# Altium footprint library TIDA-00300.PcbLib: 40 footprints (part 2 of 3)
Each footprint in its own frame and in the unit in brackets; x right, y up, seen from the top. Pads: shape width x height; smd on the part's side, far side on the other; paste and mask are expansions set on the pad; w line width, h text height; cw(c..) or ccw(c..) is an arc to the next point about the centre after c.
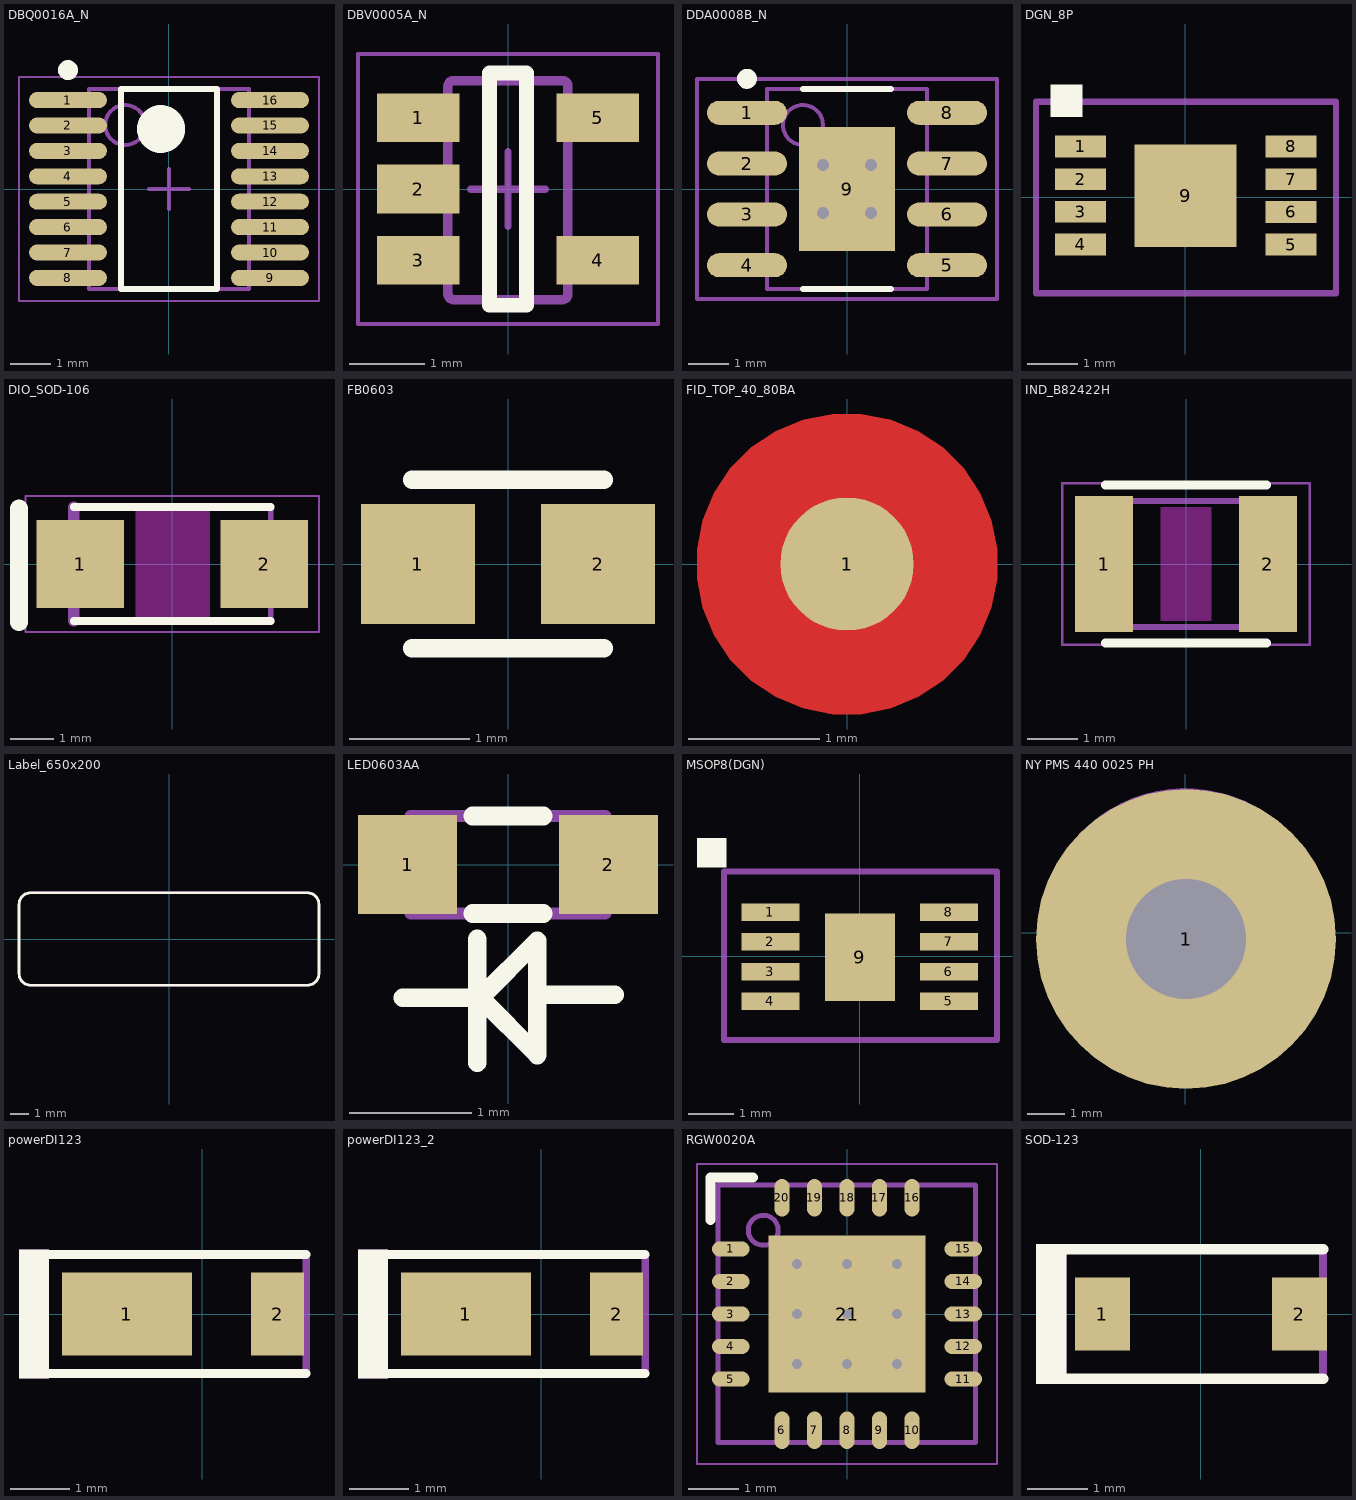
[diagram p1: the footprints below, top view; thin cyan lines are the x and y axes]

## DBQ0016A_N [mm] "SOP, 16-Leads, Body 4.9x3.9mm, Pitch 0.635mm, IPC Medium Density"
height 1.76
pads (16):
  oval 1.95x0.4 smd: 1(-2.525,2.222) 2(-2.525,1.587) 3(-2.525,0.953) 4(-2.525,0.318) 5(-2.525,-0.318) 6(-2.525,-0.953) 7(-2.525,-1.587) 8(-2.525,-2.222) 9(2.525,-2.222) 10(2.525,-1.587) 11(2.525,-0.953) 12(2.525,-0.318) 13(2.525,0.318) 14(2.525,0.953) 15(2.525,1.587) 16(2.525,2.222)
Top Overlay:
  circle w0.25: c-2.525,2.973 r0.125
  circle w0.6: c-0.2,1.5 r0.3
  lines w0.152: -1.2,-2.5 -1.2,2.5 1.2,2.5 1.2,-2.5 -1.2,-2.5
Mechanical 5:
  circle w0.1: c-1.095,1.6 r0.5
  lines w0.1: -1.995,-2.5 -1.995,2.5 1.995,2.5 1.995,-2.5 -1.995,-2.5
  text ".Designator" at -1.021,-0.548 h0.76
Mechanical 15:
  lines w0.05: -3.75,-2.8 -3.75,2.8 3.75,2.8 3.75,-2.8 -3.75,-2.8
  lines w0.1: -0.5,0 0.5,0 ; 0,-0.5 0,0.5
3D body: height 1.76, standoff 0.1, extent -1.995,-2.5 1.995,2.5

## DBV0005A_N [mm] "SOT23, 5-Leads, Body 2.9x1.6mm, Pitch 0.95mm, Lead Span 2.8mm, IPC Medium Density"
height 1.45
pads (5):
  rect 1.1x0.65 smd: 1(-1.2,0.95) 2(-1.2,0) 3(-1.2,-0.95) 4(1.2,-0.95) 5(1.2,0.95)
Top Overlay:
  lines w0.2: -0.25,-1.55 0.25,-1.55 0.25,1.55 -0.25,1.55 -0.25,-1.55
Mechanical 5:
  lines w0.127: -0.801,1.371 cw(c-0.725,1.37) -0.725,1.446 ; -0.801,1.37 -0.801,-1.399 -0.801,-1.4 ccw(c-0.725,-1.399) -0.725,-1.475 ; -0.801,1.37 -0.801,1.371 ; -0.725,-1.475 -0.725,-1.475 ; -0.725,-1.475 0.723,-1.475 0.724,-1.475 ccw(c0.723,-1.399) 0.799,-1.4 0.799,-1.399 0.799,1.37 ; -0.725,1.446 0.723,1.446 0.724,1.446 cw(c0.723,1.37) 0.799,1.371 ; -0.725,1.446 -0.725,1.446 ; 0.799,1.37 0.799,1.371 ; -1.423,-1.167 -1.199,-1.167 -1.105,-1.167 -1.088,-1.167 -0.835,-1.167 -0.801,-1.167 -0.801,-0.767 -0.835,-0.767 -1.088,-0.767 -1.105,-0.767 -1.199,-0.767 -1.423,-0.767 -1.423,-1.167 ; -1.423,-0.215 -1.199,-0.215 -1.105,-0.215 -1.088,-0.215 -0.835,-0.215 -0.801,-0.215 -0.801,0.186 -0.835,0.186 -1.088,0.186 -1.105,0.186 -1.199,0.186 -1.423,0.186 -1.423,-0.215 ; -1.423,0.738 -1.199,0.738 -1.105,0.738 -1.088,0.738 -0.835,0.738 -0.801,0.738 -0.801,1.138 -0.835,1.138 -1.088,1.138 -1.105,1.138 -1.199,1.138 -1.423,1.138 -1.423,0.738 ; 0.799,-1.167 0.799,-0.767 0.834,-0.767 1.087,-0.767 1.103,-0.767 1.198,-0.767 1.422,-0.767 1.422,-1.167 1.198,-1.167 1.103,-1.167 1.087,-1.167 0.834,-1.167 0.799,-1.167 ; 0.799,0.738 0.799,1.138 0.834,1.138 1.087,1.138 1.103,1.138 1.198,1.138 1.422,1.138 1.422,0.738 1.198,0.738 1.103,0.738 1.087,0.738 0.834,0.738 0.799,0.738
  text ".Designator" at 0.381,-0.762 h0.76
Mechanical 15:
  lines w0.05: -2,-1.8 -2,1.8 2,1.8 2,-1.8 -2,-1.8
  lines w0.1: -0.5,0 0.5,0 ; 0,-0.5 0,0.5
3D body "DBV0005AaksMF05A.stp": height 1.08, standoff -0.01, extent -1.422,-1.461 1.422,1.46

## DDA0008B_N [mm] "SOIC, 8-Leads, Body 4.9x3.9mm, Pitch 1.27mm, Exposed Pad, IPC Medium Density"
height 1.68
pads (9):
  oval 2x0.6 smd: 1(-2.5,1.905) 2(-2.5,0.635) 3(-2.5,-0.635) 4(-2.5,-1.905) 5(2.5,-1.905) 6(2.5,-0.635) 7(2.5,0.635) 8(2.5,1.905)
  rect 2.41x3.1 smd: 9(0,0)
via -0.6,-0.6 diameter 0.66 hole 0.305
via 0.6,-0.6 diameter 0.66 hole 0.305
via 0.6,0.6 diameter 0.66 hole 0.305
via -0.6,0.6 diameter 0.66 hole 0.305
Top Overlay:
  circle w0.25: c-2.5,2.755 r0.125
  lines w0.152: -1.1,-2.5 1.1,-2.5 ; -1.1,2.5 1.1,2.5
Mechanical 5:
  circle w0.1: c-1.1,1.6 r0.5
  lines w0.1: -2,-2.5 2,-2.5 2,2.5 -2,2.5 -2,-2.5
  text ".Designator" at 0.635,-0.889 h0.76
Mechanical 15:
  lines w0.1: -0.5,0 0.5,0 ; 0,-0.5 0,0.5 ; -3.75,-2.75 3.75,-2.75 3.75,2.75 -3.75,2.75 -3.75,-2.75
3D body: height 1.68, standoff 0.03, extent -2,-2.5 2,2.5

## DGN_8P [mil]
pads (9):
  rect 40x17 smd: 1(-82.1,40) 2(-82.1,14.4) 3(-82.1,-11.2) 4(-82.1,-36.8) 5(82.9,-36.9) 6(82.9,-11.3) 7(82.9,14.3) 8(82.9,40)
  rect 80x80 smd: 9(0.2,1.4)
Top Overlay:
  region: -105.6,88.3 -80.6,88.3 -80.6,63.3 -105.6,63.3
Mechanical 5:
  lines w5: -117,-75 118,-75 118,75 -117,75 -117,-75
  text "*" at -105,30 h40
  text ".Designator" at -39.6,-11.2 h40

## DIO_SOD-106 [mm] "ZENERDIODE, SOD-106"
height 2.4
pads (2):
  rect 2x2 smd: 1(-2.1,0) 2(2.1,0)
Top Layer keep-out:
  rectangle: -0.838,-1.3 0.864,1.3
Top Overlay:
  lines w0.178: -2.25,-1.3 2.25,-1.3 ; -2.25,1.3 2.25,1.3
  lines w0.406: -3.5,-1.33 -3.5,1.27
Mechanical 5:
  lines w0.127: -2.25,1.3 2.25,1.3 2.25,-1.3
  lines w0.178: -2.25,-1.3 2.25,-1.3
  lines w0.254: -2.25,-1.3 -2.25,1.3
  text ".Designator" at 1.168,0.406 h1.02
Mechanical 15:
  lines w0.05: -3.35,-1.55 3.35,-1.55 3.35,1.55 -3.35,1.55 -3.35,-1.55
3D body: height 2.4, standoff 0, extent -2.25,-1.3 2.25,1.3
3D body: height 0.5, standoff 0, extent -0.51,-0.24 0.51,0.24

## FB0603 [mm]
height 0.95
pads (2):
  rect 0.95x1 smd: 1(-0.75,0) 2(0.75,0)
Top Overlay:
  lines w0.152: -0.8,-0.703 0.8,-0.703 ; -0.8,0.703 0.8,0.703
Mechanical 15:
  lines w0.025: -0.8,-0.4 -0.8,0.4 ; 0.8,-0.4 0.8,0.4
  lines w0.1: -0.8,-0.4 -0.8,0.4

## FID_TOP_40_80BA [mil]
pads (1):
  round 40 smd mask+20: 1(0,0)
Top Layer:
  region: 45,0 45,4.43 43.27,13.13 39.88,21.32 34.95,28.69 28.69,34.95 21.32,39.88 13.13,43.27 4.43,45 0,45 -4.43,45 -13.13,43.27 -21.32,39.88 -28.69,34.95 -34.95,28.69 -39.88,21.32 -43.27,13.13 -45,4.43 -45,0 -45,-4.43 -43.27,-13.13 -39.88,-21.32 -34.95,-28.69 -28.69,-34.95 -21.32,-39.88 -13.13,-43.27 -4.43,-45 0,-45 4.43,-45 13.13,-43.27 21.32,-39.88 28.69,-34.95 34.95,-28.69 39.88,-21.32 43.27,-13.13 45,-4.43

## IND_B82422H [mm]
height 2.4
pads (2):
  rect 1.15x2.7 smd: 1(-1.625,0) 2(1.625,0)
Top Layer keep-out:
  rectangle: -0.508,-1.135 0.508,1.131
Top Overlay:
  lines w0.178: -1.6,-1.566 1.6,-1.566 ; -1.6,1.566 1.6,1.566
Mechanical 5:
  lines w0.127: -1.6,-1.25 1.6,-1.25 1.6,1.25 -1.6,1.25 -1.6,-1.25
  text ".Designator" at -0.762,-0.381 h0.76
Mechanical 15:
  lines w0.05: -2.45,-1.6 2.45,-1.6 2.45,1.6 -2.45,1.6 -2.45,-1.6
3D body: height 2.4, standoff 0, extent -1.6,-1.25 1.6,1.25

## Label_650x200 [mm] "Thermal Transfer Label"
height 0.025
Top Overlay:
  lines w0.152: -8.255,-1.905 ccw(c-7.62,-1.905) -7.62,-2.54 7.62,-2.54 ccw(c7.62,-1.905) 8.255,-1.905 8.255,1.905 ccw(c7.62,1.905) 7.62,2.54 -7.62,2.54 ccw(c-7.62,1.905) -8.255,1.905 -8.255,-1.905
Mechanical 5:
  lines w0.127: -8.255,-1.905 ccw(c-7.62,-1.905) -7.62,-2.54 7.62,-2.54 ccw(c7.62,-1.905) 8.255,-1.905 8.255,1.905 ccw(c7.62,1.905) 7.62,2.54 -7.62,2.54 ccw(c-7.62,1.905) -8.255,1.905 -8.255,-1.905
  text ".Designator" at -1.524,-0.508 h0.76
3D body: height 0.03, standoff 0, extent -8.256,-2.541 8.256,2.541

## LED0603AA [mil]
height 35.43
pads (2):
  rect 32x32 smd: 1(-32.48,0) 2(32.48,0)
Top Overlay:
  lines w6: -34,-43 -9,-43 ; -11.42,-15.75 11.42,-15.75 ; -11.42,15.75 11.42,15.75 ; -10,-64 -10,-24 ; 9.5,-42 34.5,-42 ; -9,-43 9.5,-24.5 9.5,-61.5 -9,-43
Mechanical 5:
  lines w4: -31.5,-15.75 31.5,-15.75 31.5,15.75 -31.5,15.75 -31.5,-15.75
  text ".Designator" at -42,14 h30

## MSOP8(DGN) [mil]
pads (9):
  rect 50x15 smd: 1(-77,38) 2(-77,12.4) 3(-77,-13.2) 4(-77,-38.8) 5(76.6,-38.8) 6(76.6,-13.2) 7(76.6,12.4) 8(76.6,38)
  rect 60x75 smd: 9(0,-0.8)
Top Overlay:
  region: -140.2,101.8 -115.2,101.8 -115.2,76.8 -140.2,76.8
  region: -140.2,101.8 -115.2,101.8 -115.2,76.8 -140.2,76.8
Mechanical 5:
  lines w5: -117,-72 118,-72 118,73 -117,73 -117,-72
  text "*" at -105,30 h30
  text ".Designator" at 26,17.2 h40

## NY PMS 440 0025 PH [mm] "4-40 nylon screw and mounting hole"
height 1.905
pads (1):
  round 8 hole 3.2: 1(0.021,-0.172)
Mechanical 5:
  circle w0.127: c0,0 r3.789
  text ".Designator" at -1.524,-0.508 h1.02
3D body "B_F_NY PMS 440 0025 PH.stp": height 2.69, standoff -8.74, extent -3.302,-3.3 3.296,3.3

## powerDI123 [mm] "Diodes Inc recommended land pattern, document number DS30628 Rev. 6-2"
height 1
pads (2):
  rect 2.2x1.4 smd: 1(-1.275,0)
  rect 0.9x1.4 smd: 2(1.275,0)
Top Overlay:
  rectangle: -3.099,-1.092 -2.591,1.092
  lines w0.152: -2.946,-1.003 1.759,-1.003 ; -2.946,1.003 1.759,1.003
Mechanical 5:
  rectangle: -3.099,-1.092 -2.591,1.092
  lines w0.127: -2.946,-1.003 1.759,-1.003 1.759,1.003 -2.946,1.003
  text ".Designator" at -0.813,-0.432 h0.76
3D body "PowerDI123.stp": height 1, standoff 0, extent -2.375,-0.965 1.525,0.965

## powerDI123_2 [mm]
pads (2):
  rect 2.2x1.4 smd: 1(-1.275,0)
  rect 0.9x1.4 smd: 2(1.275,0)
Top Overlay:
  rectangle: -3.099,-1.091 -2.591,1.094
  lines w0.152: -2.946,-1.003 1.759,-1.003 ; -2.946,1.003 1.759,1.003
Mechanical 5:
  rectangle: -3.099,-1.091 -2.591,1.094
  lines w0.127: -2.946,-1.003 1.759,-1.003 1.759,1.003 -2.946,1.003
  text ".Designator" at 0.432,0.406 h0.76
3D body "PowerDI123.stp": height 1, standoff 0, extent -2.375,-0.965 1.525,0.965

## RGW0020A [mm] "QFN, 20-Leads, Body 5x5mm, Pitch 0.65mm, Thermal Pad 3.15x3.15mm, TI Recommended"
height 1
pads (21):
  oval 0.75x0.3 smd mask+0.07: 1(-2.325,1.3) 2(-2.325,0.65) 3(-2.325,0) 4(-2.325,-0.65) 5(-2.325,-1.3) 11(2.325,-1.3) 12(2.325,-0.65) 13(2.325,0) 14(2.325,0.65) 15(2.325,1.3)
  oval 0.3x0.75 smd mask+0.07: 6(-1.3,-2.325) 7(-0.65,-2.325) 8(0,-2.325) 9(0.65,-2.325) 10(1.3,-2.325) 16(1.3,2.325) 17(0.65,2.325) 18(0,2.325) 19(-0.65,2.325) 20(-1.3,2.325)
  rect 3.15x3.15 smd paste-1.575 mask+0.07: 21(0,0)
via 1,-1 diameter 0.508 hole 0.203
via 0,-1 diameter 0.508 hole 0.203
via -1,-1 diameter 0.508 hole 0.203
via 1,0 diameter 0.508 hole 0.203
via 0,0 diameter 0.508 hole 0.203
via -1,0 diameter 0.508 hole 0.203
via 1,1 diameter 0.508 hole 0.203
via 0,1 diameter 0.508 hole 0.203
via -1,1 diameter 0.508 hole 0.203
Top Overlay:
  lines w0.2: -2.725,1.875 -2.725,2.725 -1.875,2.725
Top Paste:
  rectangle: 0.1,-1.468 1.468,-0.1
  region: -0.1,-0.1 -1.468,-0.1 -1.468,-1.468 -0.1,-1.468
  region: -0.1,1.468 -1.468,1.468 -1.468,0.1 -0.1,0.1
  rectangle: 0.1,0.1 1.468,1.468
Mechanical 5:
  circle w0.1: c-1.675,1.675 r0.3
  lines w0.1: -2.575,-2.575 2.575,-2.575 2.575,2.575 -2.575,2.575 -2.575,-2.575
  text ".Designator" at 0.432,-0.889 h1.02
Mechanical 15:
  lines w0.05: -3,-3 3,-3 3,3 -3,3 -3,-3
  lines w0.1: -0.5,0 0.5,0 ; 0,-0.5 0,0.5
3D body: height 1, standoff 0, extent -2.575,-2.575 2.575,2.575
3D body: height 1.01, standoff 0.5, extent -1.974,1.376 -1.376,1.974

## SOD-123 [mm] "On Semi recommended land pattern"
height 1.35
pads (2):
  rect 0.915x1.22 smd: 1(-1.637,0) 2(1.637,0)
Top Overlay:
  rectangle: -2.743,-1.168 -2.235,1.168
  lines w0.178: -2.413,-1.079 2.032,-1.079 ; -2.413,1.079 2.032,1.079
Mechanical 5:
  rectangle: -2.743,-1.168 -2.235,1.168
  lines w0.127: -2.413,-1.079 2.032,-1.079 2.032,1.079 -2.413,1.079
  text ".Designator" at -0.711,-0.356 h0.76
3D body "SOD-123.stp": height 1.35, standoff 0, extent -1.932,-0.9 1.932,0.9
